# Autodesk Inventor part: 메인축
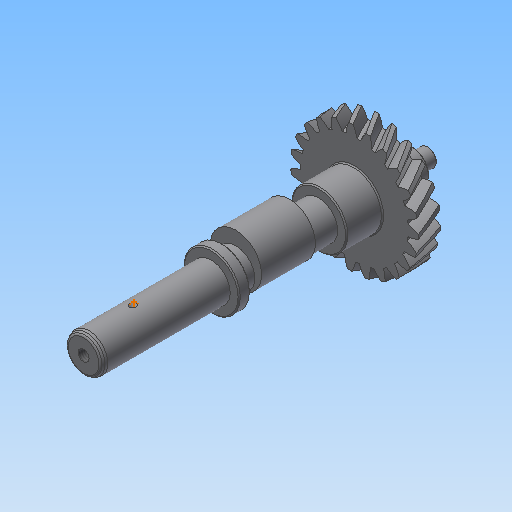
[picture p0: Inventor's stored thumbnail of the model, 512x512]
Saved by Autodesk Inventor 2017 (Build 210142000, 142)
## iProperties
Created: 2016-12
Part Number: 메인축
Material: 강철, 탄소
Document SubType Name: Modeling
Designer: mduedu
Categories: <?xml version="1.0" encoding="UTF-16"?> <MemberInstance><Categories><FamilyTemplate><FamilyTemplateParameter ValueType="xs:double" Id="1" ObjectReferenceKey="da
Density: 7.87 g/cm^3
Appearance: 기본값
Mass: 488.962 g
Surface Area: 171.638 cm^2
Volume: 62.1298 cm^3
CustomPartVersion: 1
Author: mduedu
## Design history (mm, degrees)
sketch "Sketch1"
  geometry: C1 r 28.558 at (0, 0)
  constraints: 1 centre point
  dimensions: "d0" = 57.11622 diameter of C1 (= da_da)
extrude "Extrusion1" new body sketch "Sketch1" distance "d1" = 10 (= da_b); taper "d2" = 0 deg
workplane "Work Plane2"
sketch "Sketch2"
  geometry: C1 r 28.558 at (0, 0) reference; C2 r 26.558 at (0, 0)
  constraints: 1 centre point, 1 coincident
  dimensions: "d3" = 53.11622 diameter of C2 (= da_dw)
feature "피치 지름" sketch "Sketch2" dims "d4" = 10, "d5" = 0
workplane "Work Plane8"
workplane "Work Plane9"
feature "스퍼 기어" dims "d34" = 1.36591 (computed from da_z), "da_b" = 10, "da_d" = 53.11622, "da_aw" = 43.87862, "da_da" = 57.11622, "da_df" = 48.11622, "da_dw" = 53.11622, angle "da_beta" = 30 deg, "da_lefttooth" = 10, "da_righttooth" = 0
sketch "스케치3"
  geometry: C1 r 12.5 at (0, 0); 1 further point
  constraints: 1 centre point, 1 coincident
  dimensions: "d49" = 25 diameter of C1
extrude "돌출2" join sketch "스케치3" distance "d50" = 16; taper "d51" = 0 deg
sketch "스케치4"
  geometry: C1 r 8.5 at (0, 0); 1 further point
  constraints: 1 centre point, 1 coincident
  dimensions: "d52" = 17 diameter of C1
extrude "돌출3" join sketch "스케치4" distance "d53" = 105; taper "d54" = 0 deg
sketch "스케치5"
  geometry: C1 r 7.5 at (0, 0); 1 further point
  constraints: 1 centre point, 1 coincident
  dimensions: "d55" = 15 diameter of C1
extrude "돌출4" join sketch "스케치5" distance "d56" = 16; taper "d57" = 0 deg
sketch "스케치6"
  geometry: C1 r 4 at (0, 0); 1 further point
  constraints: 1 centre point, 1 coincident
  dimensions: "d58" = 8 diameter of C1
extrude "돌출5" join sketch "스케치6" distance "d59" = 7; taper "d60" = 0 deg
chamfer "모따기1" distance "d61" = 0.5; stored, may be unused: second distance "d62" = 2, angle "d63" = 45 deg
fillet "모깎기1" dims "d64" = 0.5
node "작업 평면11"
sketch "스케치7"
  geometry: C1 r 11.5 at (0, 3); C2 r 8.5 at (0, 0) reference; 1 further point
  constraints: 1 centre point, 1 tangent, 1 vertical alignment
  dimensions: "d66" = 3 distance of point (0, 0) C1.centre; "d67" = 23 diameter of C1 (derived)
extrude "돌출6" join sketch "스케치7" stored distance "d68" = 24; taper "d69" = 0 deg
node "작업 평면12"
sketch "스케치8"
  geometry: C1 r 12.5 at (0, 0) reference; 1 further point
extrude "돌출7" join sketch "스케치8" distance "d71" = 5; taper "d72" = 0 deg
chamfer "모따기2" distance "d73" = 0.5; stored, may be unused: second distance "d74" = 2, angle "d75" = 45 deg
node "작업 평면13"
sketch "스케치9" dims "d81" = 18
  geometry: L1 (2.5, 95.5)-(-2.5, 95.5); L2 (-2.5, 95.5)-(-2.5, 82.5); L3 (-2.5, 82.5)-(2.5, 82.5); L4 (2.5, 82.5)-(2.5, 95.5); L5 (8.5, 105)-(-8.5, 105) reference; 3 further points
  constraints: 8 end point, 2 horizontal alignment, 2 midpoint, 2 parallel, 1 horizontal, 1 perpendicular, 1 vertical alignment, 4 other
  dimensions: "d79" = 5 distance between parallel lines of L2 L4; "d98" = 7 dimension on L5
extrude "돌출8" cut sketch "스케치9" distance "d83" = 3; taper "d84" = 0 deg
sketch "스케치10"
  geometry: L1 (-8.5, 74)-(-8.5, 131) reference; L2 (8.5, 74)-(8.5, 131) reference; L3 (8.5, 109)-(-8.5, 109); L4 (8.5, 109)-(7, 109); L5 (7, 109)-(8.5, 107.5); L6 (8.5, 107.5)-(8.5, 109); L7 (8.5, 131)-(-8.5, 131) reference; 1 further point
  constraints: 8 end point, 4 point on line, 2 perpendicular
  dimensions: "d86" = 45 deg angle of L5 L4; "d87" = 3 diameter of L5.end L3; "d99" = 22 distance between parallel lines of L7 L3
revolve "회전1" stored, may be unused: angle "d88" = 90 deg
sketch "스케치11"
  geometry: L1 (-8.5, 74)-(-8.5, 131) reference; L2 (-40.7, 131)-(40.7, 131) reference; L3 (-7.45, 131)-(-8.5, 129.181); L4 (0, 131)-(0, 0); L5 (-8.5, 129.181)-(-8.5, 131); L6 (-7.45, 131)-(-8.5, 131)
  constraints: 8 end point, 2 perpendicular, 2 point on line, 1 collinear, 1 midpoint
  dimensions: "d100" = 30 deg angle of L1 L3; "d101" = 14.9 diameter of L3.start L4
revolve "회전2" sketch "스케치11" stored, may be unused: angle "d102" = 90 deg
fillet "모깎기2" dims "d103" = 2, "d113" = 1
hole "구멍2" diameter "d106" = 4.917; stored, may be unused: countersink angle "d110" = 90 deg, drill point angle "d112" = 118 deg; dims "d104" = 10, "d105" = 10, "d107" = 10, "d108" = 4, "d109" = 2, "d111" = 12
node "작업점1"
body "Solid1"
body "Srf1"
node "참조1"
other parameters: "d16" = 43.87862 (= da_aw), "d17" = 0, "d39" = 0, "d41" = 0, "d43" = 43.87862 (= da_aw), "d46" = 43.87862 (= da_aw), "d47" = 0, "d48" = 0, "d65" = 25, "d70" = 48
